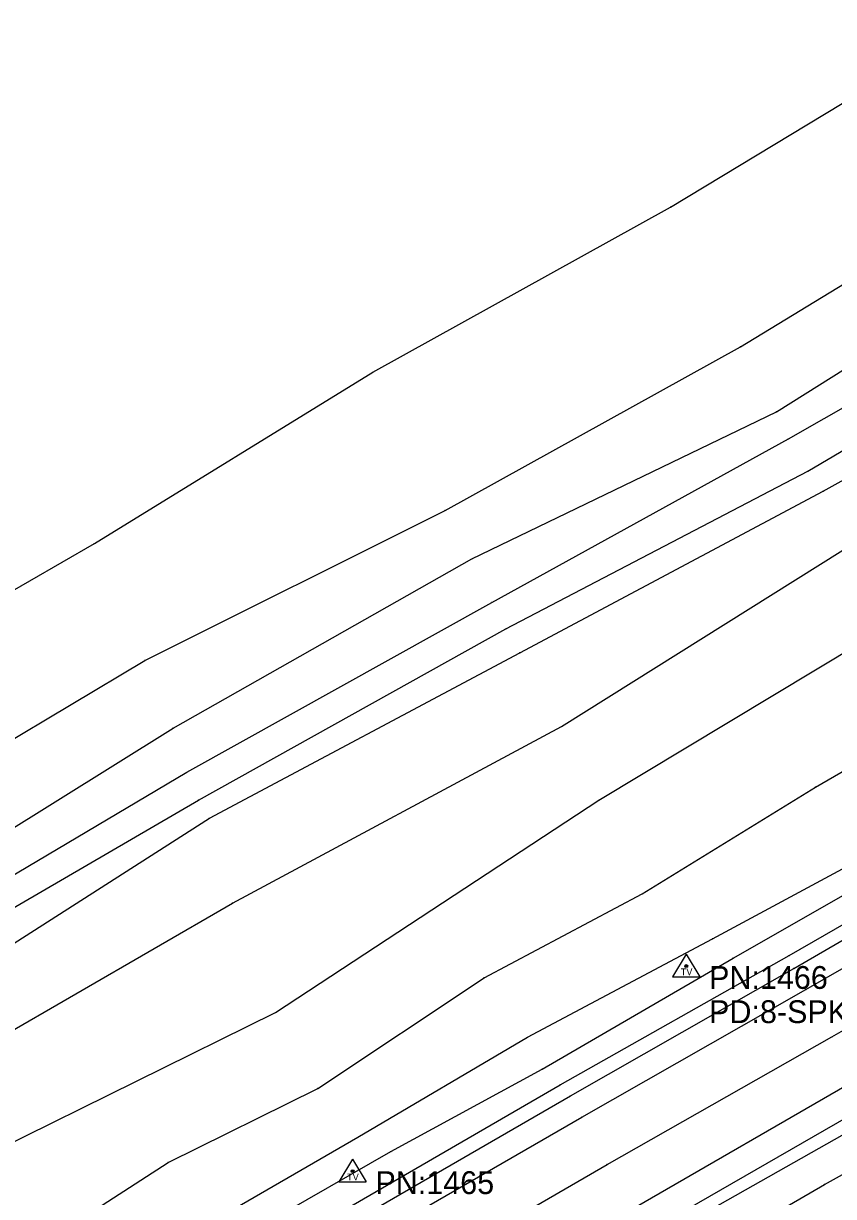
# Model space of a CAD drawing. Extents: x 1419505 to 1434054, y 1956910 to 1968644.
# Drawn here: x 1422539.1 to 1422716.6, y 1958723.8 to 1958981 of the extents above; entities that cross this region are included whole.
import ezdxf

# ---------------------------------------------------------------- set-up
doc = ezdxf.new("R2010")
doc.units = 0
for name, color, linetype in [('S_BREAKLINE', 7, 'Continuous'), ('S_DITCHLINE', 7, 'Continuous'), ('S_EDGE_PAVEMENT', 7, 'Continuous'), ('S_GRD_PT_SYM', 7, 'Continuous'), ('S_PAVEMENT_CROWN', 7, 'Continuous'), ('S_RDW_PT_SYM', 7, 'Continuous'), ('S_SECONDARY_CTL', 7, 'Continuous'), ('S_SECONDARY_CTL_ANNOT', 7, 'Continuous'), ('S_SHOULDER', 7, 'Continuous')]:
    doc.layers.add(name, color=color, linetype=linetype)

msp = doc.modelspace()

# ---------------------------------------------------------------- linework, layer by layer
at = {"layer": 'S_BREAKLINE'}
for p, q in [((1422680.8713, 1958940.6924), (1422747.5446, 1958980.981)), ((1422696.1713, 1958910.1255), (1422764.9527, 1958951.8852)), ((1422615.6481, 1958904.5521), (1422680.8713, 1958940.6924)), ((1422704.0708, 1958895.8675), (1422772.8152, 1958939.0653)), ((1422714.3205, 1958878.4334), (1422785.8341, 1958918.713)), ((1422631.4631, 1958874.2321), (1422696.1713, 1958910.1255)), ((1422554.6682, 1958866.9687), (1422615.6481, 1958904.5521)), ((1422637.3475, 1958863.6005), (1422704.0708, 1958895.8675)), ((1422647.8492, 1958843.0041), (1422714.3205, 1958878.4334)), ((1422565.6719, 1958841.303), (1422631.4631, 1958874.2321)), ((1422471.5218, 1958819.2336), (1422554.6682, 1958866.9687)), ((1422656.9928, 1958826.8241), (1422718.6307, 1958865.5316)), ((1422571.8633, 1958826.5221), (1422637.3475, 1958863.6005)), ((1422665.1803, 1958810.731), (1422728.1394, 1958848.5945)), ((1422484.1426, 1958792.6359), (1422565.6719, 1958841.303)), ((1422579.8628, 1958806.7668), (1422647.8492, 1958843.0041)), ((1422712.6394, 1958813.5882), (1422738.182, 1958828.4412)), ((1422491.2591, 1958776.0958), (1422571.8633, 1958826.5221)), ((1422584.8771, 1958788.1346), (1422656.9928, 1958826.8241)), ((1422674.6769, 1958790.1587), (1422712.6394, 1958813.5882)), ((1422594.3317, 1958764.139), (1422665.1803, 1958810.731)), ((1422502.2028, 1958757.1546), (1422579.8628, 1958806.7668)), ((1422706.891, 1958776.6798), (1422756.4312, 1958805.1607)), ((1422690.0639, 1958780.2881), (1422725.1792, 1958799.2663)), ((1422694.5982, 1958776.0848), (1422726.9303, 1958794.569)), ((1422640.0367, 1958771.7955), (1422674.6769, 1958790.1587)), ((1422507.7021, 1958743.5137), (1422584.8771, 1958788.1346)), ((1422649.5633, 1958758.7207), (1422690.0639, 1958780.2881)), ((1422656.6707, 1958748.282), (1422706.891, 1958776.6798)), ((1422652.7505, 1958751.7062), (1422694.5982, 1958776.0848)), ((1422603.5533, 1958747.537), (1422640.0367, 1958771.7955)), ((1422515.4536, 1958725.2285), (1422594.3317, 1958764.139)), ((1422612.3679, 1958736.8023), (1422649.5633, 1958758.7207)), ((1422619.6124, 1958733.7211), (1422652.7505, 1958751.7062)), ((1422604.9034, 1958718.2941), (1422656.6707, 1958748.282)), ((1422714.5805, 1958726.4656), (1422754.7091, 1958748.762)), ((1422570.7652, 1958731.2519), (1422603.5533, 1958747.537)), ((1422676.663, 1958713.6518), (1422725.1872, 1958741.1175)), ((1422576.6496, 1958716.1899), (1422612.3679, 1958736.8023)), ((1422579.8308, 1958710.9236), (1422619.6124, 1958733.7211)), ((1422526.6403, 1958702.7961), (1422570.7652, 1958731.2519)), ((1422664.3872, 1958697.2837), (1422714.5805, 1958726.4656))]:
    msp.add_line(p, q, dxfattribs=at)
at = {"layer": 'S_DITCHLINE'}
for p, q in [((1422706.752, 1958889.9102), (1422777.3605, 1958930.4788)), ((1422710.9763, 1958882.8447), (1422780.7508, 1958924.2814)), ((1422641.6858, 1958854.0148), (1422706.752, 1958889.9102)), ((1422644.8, 1958848.2705), (1422710.9763, 1958882.8447)), ((1422574.9015, 1958816.8324), (1422641.6858, 1958854.0148)), ((1422577.3946, 1958810.704), (1422644.8, 1958848.2705)), ((1422495.3633, 1958769.7824), (1422574.9015, 1958816.8324)), ((1422498.3175, 1958764.7171), (1422577.3946, 1958810.704))]:
    msp.add_line(p, q, dxfattribs=at)
at = {"layer": 'S_EDGE_PAVEMENT'}
for p, q in [((1422710.5292, 1958769.2204), (1422760.7485, 1958798.1712)), ((1422661.4411, 1958741.1855), (1422710.5292, 1958769.2204)), ((1422673.3998, 1958721.6573), (1422721.0009, 1958749.1051)), ((1422608.3336, 1958710.6156), (1422661.4411, 1958741.1855))]:
    msp.add_line(p, q, dxfattribs=at)
at = {"layer": 'S_GRD_PT_SYM'}
for points in [[(1422680.8713, 1958940.6924), (1422680.8713, 1958940.7424), (1422680.8713, 1958940.6924), (1422680.8213, 1958940.6924), (1422680.8713, 1958940.6924), (1422680.8713, 1958940.6424), (1422680.8713, 1958940.6924), (1422680.9213, 1958940.6924)], [(1422696.1713, 1958910.1255), (1422696.1713, 1958910.1755), (1422696.1713, 1958910.1255), (1422696.1213, 1958910.1255), (1422696.1713, 1958910.1255), (1422696.1713, 1958910.0755), (1422696.1713, 1958910.1255), (1422696.2213, 1958910.1255)], [(1422615.6481, 1958904.5521), (1422615.6481, 1958904.6021), (1422615.6481, 1958904.5521), (1422615.5981, 1958904.5521), (1422615.6481, 1958904.5521), (1422615.6481, 1958904.5021), (1422615.6481, 1958904.5521), (1422615.6981, 1958904.5521)], [(1422704.0708, 1958895.8675), (1422704.0708, 1958895.9175), (1422704.0708, 1958895.8675), (1422704.0208, 1958895.8675), (1422704.0708, 1958895.8675), (1422704.0708, 1958895.8175), (1422704.0708, 1958895.8675), (1422704.1208, 1958895.8675)], [(1422706.752, 1958889.9102), (1422706.752, 1958889.9602), (1422706.752, 1958889.9102), (1422706.702, 1958889.9102), (1422706.752, 1958889.9102), (1422706.752, 1958889.8602), (1422706.752, 1958889.9102), (1422706.802, 1958889.9102)], [(1422710.9763, 1958882.8447), (1422710.9763, 1958882.8947), (1422710.9763, 1958882.8447), (1422710.9263, 1958882.8447), (1422710.9763, 1958882.8447), (1422710.9763, 1958882.7947), (1422710.9763, 1958882.8447), (1422711.0263, 1958882.8447)], [(1422714.3205, 1958878.4334), (1422714.3205, 1958878.4834), (1422714.3205, 1958878.4334), (1422714.2705, 1958878.4334), (1422714.3205, 1958878.4334), (1422714.3205, 1958878.3834), (1422714.3205, 1958878.4334), (1422714.3705, 1958878.4334)], [(1422631.4631, 1958874.2321), (1422631.4631, 1958874.2821), (1422631.4631, 1958874.2321), (1422631.4131, 1958874.2321), (1422631.4631, 1958874.2321), (1422631.4631, 1958874.1821), (1422631.4631, 1958874.2321), (1422631.5131, 1958874.2321)], [(1422554.6682, 1958866.9687), (1422554.6682, 1958867.0187), (1422554.6682, 1958866.9687), (1422554.6182, 1958866.9687), (1422554.6682, 1958866.9687), (1422554.6682, 1958866.9187), (1422554.6682, 1958866.9687), (1422554.7182, 1958866.9687)], [(1422637.3475, 1958863.6005), (1422637.3475, 1958863.6505), (1422637.3475, 1958863.6005), (1422637.2975, 1958863.6005), (1422637.3475, 1958863.6005), (1422637.3475, 1958863.5505), (1422637.3475, 1958863.6005), (1422637.3975, 1958863.6005)], [(1422641.6858, 1958854.0148), (1422641.6858, 1958854.0648), (1422641.6858, 1958854.0148), (1422641.6358, 1958854.0148), (1422641.6858, 1958854.0148), (1422641.6858, 1958853.9648), (1422641.6858, 1958854.0148), (1422641.7358, 1958854.0148)], [(1422644.8, 1958848.2705), (1422644.8, 1958848.3205), (1422644.8, 1958848.2705), (1422644.75, 1958848.2705), (1422644.8, 1958848.2705), (1422644.8, 1958848.2205), (1422644.8, 1958848.2705), (1422644.85, 1958848.2705)], [(1422647.8492, 1958843.0041), (1422647.8492, 1958843.0541), (1422647.8492, 1958843.0041), (1422647.7992, 1958843.0041), (1422647.8492, 1958843.0041), (1422647.8492, 1958842.9541), (1422647.8492, 1958843.0041), (1422647.8992, 1958843.0041)], [(1422565.6719, 1958841.303), (1422565.6719, 1958841.353), (1422565.6719, 1958841.303), (1422565.6219, 1958841.303), (1422565.6719, 1958841.303), (1422565.6719, 1958841.253), (1422565.6719, 1958841.303), (1422565.7219, 1958841.303)], [(1422571.8633, 1958826.5221), (1422571.8633, 1958826.5721), (1422571.8633, 1958826.5221), (1422571.8133, 1958826.5221), (1422571.8633, 1958826.5221), (1422571.8633, 1958826.4721), (1422571.8633, 1958826.5221), (1422571.9133, 1958826.5221)], [(1422656.9928, 1958826.8241), (1422656.9928, 1958826.8741), (1422656.9928, 1958826.8241), (1422656.9428, 1958826.8241), (1422656.9928, 1958826.8241), (1422656.9928, 1958826.7741), (1422656.9928, 1958826.8241), (1422657.0428, 1958826.8241)], [(1422574.9015, 1958816.8324), (1422574.9015, 1958816.8824), (1422574.9015, 1958816.8324), (1422574.8515, 1958816.8324), (1422574.9015, 1958816.8324), (1422574.9015, 1958816.7824), (1422574.9015, 1958816.8324), (1422574.9515, 1958816.8324)], [(1422712.6394, 1958813.5882), (1422712.6394, 1958813.6382), (1422712.6394, 1958813.5882), (1422712.5894, 1958813.5882), (1422712.6394, 1958813.5882), (1422712.6394, 1958813.5382), (1422712.6394, 1958813.5882), (1422712.6894, 1958813.5882)], [(1422577.3946, 1958810.704), (1422577.3946, 1958810.754), (1422577.3946, 1958810.704), (1422577.3446, 1958810.704), (1422577.3946, 1958810.704), (1422577.3946, 1958810.654), (1422577.3946, 1958810.704), (1422577.4446, 1958810.704)], [(1422665.1803, 1958810.731), (1422665.1803, 1958810.781), (1422665.1803, 1958810.731), (1422665.1303, 1958810.731), (1422665.1803, 1958810.731), (1422665.1803, 1958810.681), (1422665.1803, 1958810.731), (1422665.2303, 1958810.731)], [(1422579.8628, 1958806.7668), (1422579.8628, 1958806.8168), (1422579.8628, 1958806.7668), (1422579.8128, 1958806.7668), (1422579.8628, 1958806.7668), (1422579.8628, 1958806.7168), (1422579.8628, 1958806.7668), (1422579.9128, 1958806.7668)], [(1422674.6769, 1958790.1587), (1422674.6769, 1958790.2087), (1422674.6769, 1958790.1587), (1422674.6269, 1958790.1587), (1422674.6769, 1958790.1587), (1422674.6769, 1958790.1087), (1422674.6769, 1958790.1587), (1422674.7269, 1958790.1587)], [(1422584.8771, 1958788.1346), (1422584.8771, 1958788.1846), (1422584.8771, 1958788.1346), (1422584.8271, 1958788.1346), (1422584.8771, 1958788.1346), (1422584.8771, 1958788.0846), (1422584.8771, 1958788.1346), (1422584.9271, 1958788.1346)], [(1422690.0639, 1958780.2881), (1422690.0639, 1958780.3381), (1422690.0639, 1958780.2881), (1422690.0139, 1958780.2881), (1422690.0639, 1958780.2881), (1422690.0639, 1958780.2381), (1422690.0639, 1958780.2881), (1422690.1139, 1958780.2881)], [(1422706.891, 1958776.6798), (1422706.891, 1958776.7298), (1422706.891, 1958776.6798), (1422706.841, 1958776.6798), (1422706.891, 1958776.6798), (1422706.891, 1958776.6298), (1422706.891, 1958776.6798), (1422706.941, 1958776.6798)], [(1422694.5982, 1958776.0848), (1422694.5982, 1958776.1348), (1422694.5982, 1958776.0848), (1422694.5482, 1958776.0848), (1422694.5982, 1958776.0848), (1422694.5982, 1958776.0348), (1422694.5982, 1958776.0848), (1422694.6482, 1958776.0848)], [(1422640.0367, 1958771.7955), (1422640.0367, 1958771.8455), (1422640.0367, 1958771.7955), (1422639.9867, 1958771.7955), (1422640.0367, 1958771.7955), (1422640.0367, 1958771.7455), (1422640.0367, 1958771.7955), (1422640.0867, 1958771.7955)], [(1422594.3317, 1958764.139), (1422594.3317, 1958764.189), (1422594.3317, 1958764.139), (1422594.2817, 1958764.139), (1422594.3317, 1958764.139), (1422594.3317, 1958764.089), (1422594.3317, 1958764.139), (1422594.3817, 1958764.139)], [(1422649.5633, 1958758.7207), (1422649.5633, 1958758.7707), (1422649.5633, 1958758.7207), (1422649.5133, 1958758.7207), (1422649.5633, 1958758.7207), (1422649.5633, 1958758.6707), (1422649.5633, 1958758.7207), (1422649.6133, 1958758.7207)], [(1422652.7505, 1958751.7062), (1422652.7505, 1958751.7562), (1422652.7505, 1958751.7062), (1422652.7005, 1958751.7062), (1422652.7505, 1958751.7062), (1422652.7505, 1958751.6562), (1422652.7505, 1958751.7062), (1422652.8005, 1958751.7062)], [(1422656.6707, 1958748.282), (1422656.6707, 1958748.332), (1422656.6707, 1958748.282), (1422656.6207, 1958748.282), (1422656.6707, 1958748.282), (1422656.6707, 1958748.232), (1422656.6707, 1958748.282), (1422656.7207, 1958748.282)], [(1422603.5533, 1958747.537), (1422603.5533, 1958747.587), (1422603.5533, 1958747.537), (1422603.5033, 1958747.537), (1422603.5533, 1958747.537), (1422603.5533, 1958747.487), (1422603.5533, 1958747.537), (1422603.6033, 1958747.537)], [(1422612.3679, 1958736.8023), (1422612.3679, 1958736.8523), (1422612.3679, 1958736.8023), (1422612.3179, 1958736.8023), (1422612.3679, 1958736.8023), (1422612.3679, 1958736.7523), (1422612.3679, 1958736.8023), (1422612.4179, 1958736.8023)], [(1422619.6124, 1958733.7211), (1422619.6124, 1958733.7711), (1422619.6124, 1958733.7211), (1422619.5624, 1958733.7211), (1422619.6124, 1958733.7211), (1422619.6124, 1958733.6711), (1422619.6124, 1958733.7211), (1422619.6624, 1958733.7211)], [(1422570.7652, 1958731.2519), (1422570.7652, 1958731.3019), (1422570.7652, 1958731.2519), (1422570.7152, 1958731.2519), (1422570.7652, 1958731.2519), (1422570.7652, 1958731.2019), (1422570.7652, 1958731.2519), (1422570.8152, 1958731.2519)], [(1422714.5805, 1958726.4656), (1422714.5805, 1958726.5156), (1422714.5805, 1958726.4656), (1422714.5305, 1958726.4656), (1422714.5805, 1958726.4656), (1422714.5805, 1958726.4156), (1422714.5805, 1958726.4656), (1422714.6305, 1958726.4656)]]:
    msp.add_lwpolyline(points, dxfattribs=at)
at = {"layer": 'S_PAVEMENT_CROWN'}
for p, q in [((1422716.2366, 1958758.7937), (1422767.2339, 1958788.4216)), ((1422666.9894, 1958730.8559), (1422716.2366, 1958758.7937)), ((1422612.4149, 1958699.3298), (1422666.9894, 1958730.8559))]:
    msp.add_line(p, q, dxfattribs=at)
at = {"layer": 'S_RDW_PT_SYM'}
for points in [[(1422707.8591, 1958773.8337), (1422707.8591, 1958773.8837), (1422707.8591, 1958773.8337), (1422707.8091, 1958773.8337), (1422707.8591, 1958773.8337), (1422707.8591, 1958773.7837), (1422707.8591, 1958773.8337), (1422707.9091, 1958773.8337)], [(1422710.5292, 1958769.2204), (1422710.5292, 1958769.2704), (1422710.5292, 1958769.2204), (1422710.4792, 1958769.2204), (1422710.5292, 1958769.2204), (1422710.5292, 1958769.1704), (1422710.5292, 1958769.2204), (1422710.5792, 1958769.2204)], [(1422716.2366, 1958758.7937), (1422716.2366, 1958758.8437), (1422716.2366, 1958758.7937), (1422716.1866, 1958758.7937), (1422716.2366, 1958758.7937), (1422716.2366, 1958758.7437), (1422716.2366, 1958758.7937), (1422716.2866, 1958758.7937)], [(1422658.9659, 1958745.9249), (1422658.9659, 1958745.9749), (1422658.9659, 1958745.9249), (1422658.9159, 1958745.9249), (1422658.9659, 1958745.9249), (1422658.9659, 1958745.8749), (1422658.9659, 1958745.9249), (1422659.0159, 1958745.9249)], [(1422661.4411, 1958741.1855), (1422661.4411, 1958741.2355), (1422661.4411, 1958741.1855), (1422661.3911, 1958741.1855), (1422661.4411, 1958741.1855), (1422661.4411, 1958741.1355), (1422661.4411, 1958741.1855), (1422661.4911, 1958741.1855)], [(1422666.9894, 1958730.8559), (1422666.9894, 1958730.9059), (1422666.9894, 1958730.8559), (1422666.9394, 1958730.8559), (1422666.9894, 1958730.8559), (1422666.9894, 1958730.8059), (1422666.9894, 1958730.8559), (1422667.0394, 1958730.8559)]]:
    msp.add_lwpolyline(points, dxfattribs=at)
at = {"layer": 'S_SECONDARY_CTL'}
for p, q in [((1422684.3215, 1958776.9488), (1422681.3115, 1958771.9949)), ((1422684.3215, 1958776.9488), (1422687.2688, 1958771.9949)), ((1422681.3115, 1958771.9949), (1422687.2688, 1958771.9949)), ((1422611.1998, 1958731.9739), (1422608.1898, 1958727.02)), ((1422611.1998, 1958731.9739), (1422614.1471, 1958727.02)), ((1422608.1898, 1958727.02), (1422614.1471, 1958727.02))]:
    msp.add_line(p, q, dxfattribs=at)
for centre, radius in [((1422684.3215, 1958774.3387), 0.3111), ((1422684.3215, 1958774.3387), 0.1827), ((1422684.3215, 1958774.3387), 0.1033), ((1422611.1998, 1958729.3638), 0.3111), ((1422611.1998, 1958729.3638), 0.1827), ((1422611.1998, 1958729.3638), 0.1033)]:
    msp.add_circle(centre, radius, dxfattribs=at)
at = {"layer": 'S_SHOULDER'}
for p, q in [((1422707.8591, 1958773.8337), (1422758.3413, 1958803.0565)), ((1422658.9659, 1958745.9249), (1422707.8591, 1958773.8337)), ((1422605.9155, 1958715.2549), (1422658.9659, 1958745.9249)), ((1422675.803, 1958716.0429), (1422723.193, 1958743.3637))]:
    msp.add_line(p, q, dxfattribs=at)

# ---------------------------------------------------------------- texts
at = {"layer": 'S_SECONDARY_CTL'}
for p in [(1422683.1168, 1958772.3274), (1422609.9951, 1958727.3525)]:
    msp.add_text('TV', height=1.5, rotation=360, dxfattribs=at).set_placement(p)
at = {"layer": 'S_SECONDARY_CTL_ANNOT'}
for s, p in [('PN:1466', (1422689.3215, 1958769.3387)), ('PD:8-SPK 8 SPK', (1422689.3215, 1958761.8387)), ('PN:1465', (1422616.1998, 1958724.3638))]:
    msp.add_text(s, height=5, dxfattribs=at).set_placement(p)

doc.saveas('drawing.dxf')
